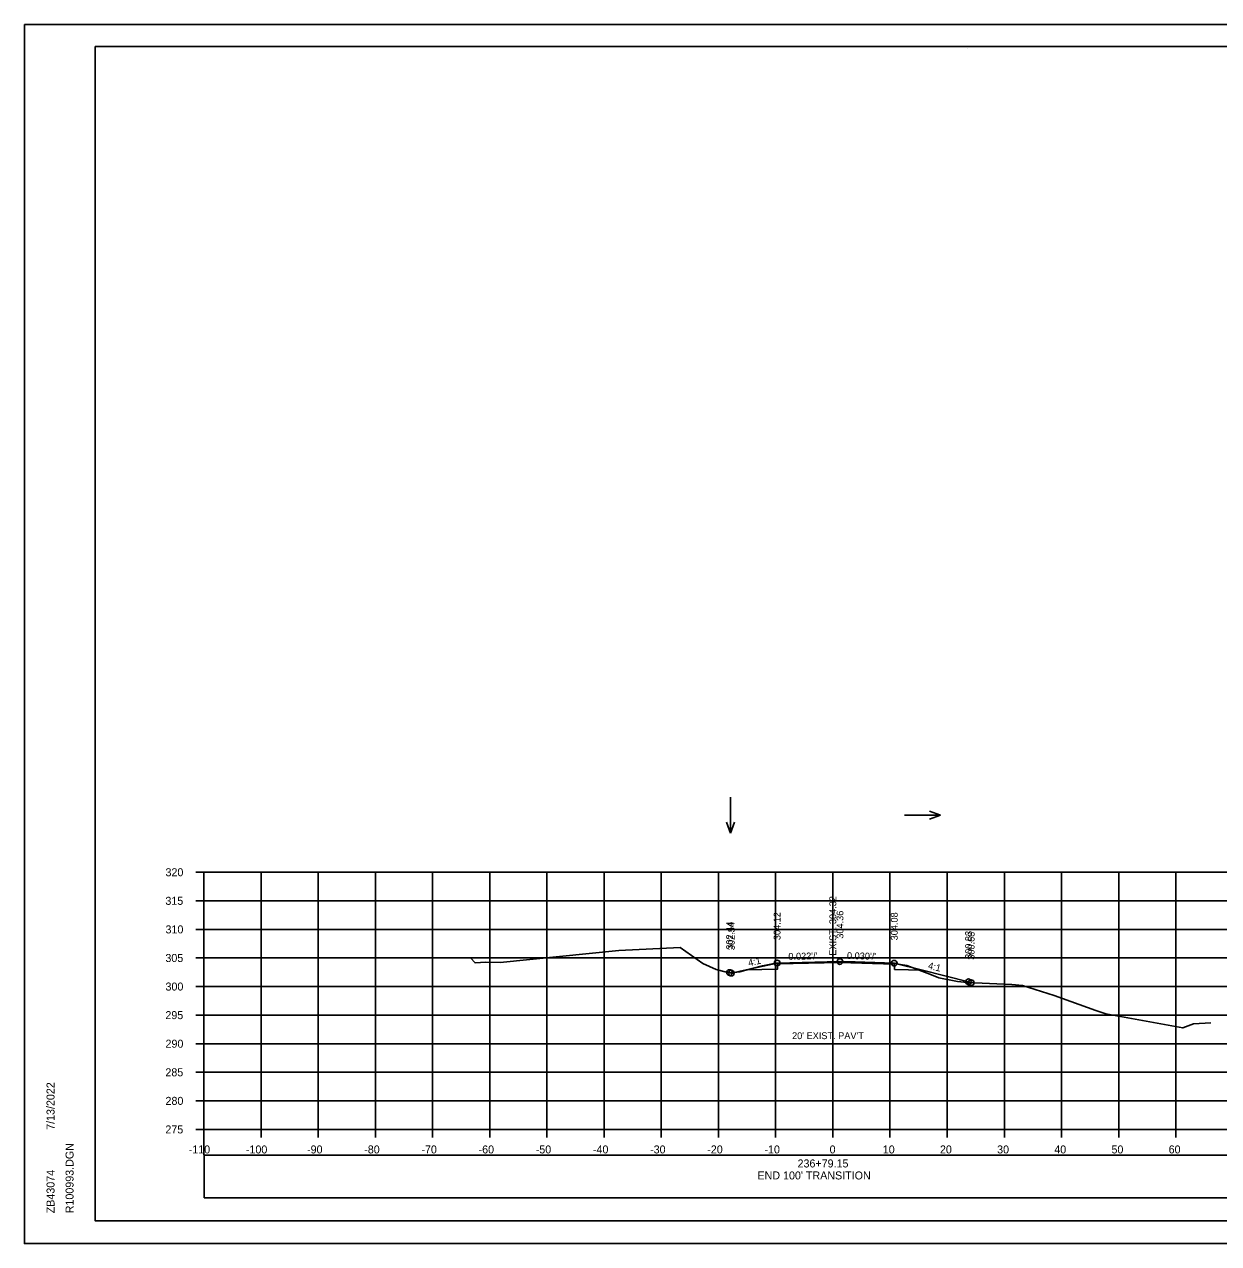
# Model space of a CAD drawing. Extents: x 4667 to 1632277, y -2100 to 724501.
# Drawn here: x 5635.8 to 5844.7, y 1663 to 1876.3 of the extents above; entities that cross this region are included whole.
import ezdxf

# ---------------------------------------------------------------- set-up
doc = ezdxf.new("R2010")
doc.units = 0
for name, color, linetype in [('R_Axis', 7, 'Continuous'), ('R_Axis Annot', 7, 'Continuous'), ('R_Border', 7, 'Continuous'), ('R_Exist Surface', 7, 'Continuous'), ('R_Grid', 7, 'Continuous'), ('R_No Plot', 7, 'Continuous'), ('R_Proposed CofA', 7, 'Continuous'), ('R_Temp Easement', 7, 'Continuous'), ('R_Water Annot', 7, 'Continuous')]:
    doc.layers.add(name, color=color, linetype=linetype)

msp = doc.modelspace()

# ---------------------------------------------------------------- linework, layer by layer
at = {"layer": 'R_Axis'}
for p, q in [((5665.78, 1727.96), (5667.18, 1727.96)), ((5667.18, 1682.96), (5667.18, 1727.96)), ((5665.78, 1722.96), (5667.18, 1722.96)), ((5665.78, 1717.96), (5667.18, 1717.96)), ((5665.78, 1712.96), (5667.18, 1712.96)), ((5665.78, 1707.96), (5667.18, 1707.96)), ((5665.78, 1702.96), (5667.18, 1702.96)), ((5665.78, 1697.96), (5667.18, 1697.96)), ((5665.78, 1692.96), (5667.18, 1692.96)), ((5665.78, 1687.96), (5667.18, 1687.96)), ((5665.78, 1682.96), (5667.18, 1682.96)), ((5667.18, 1682.96), (5947.18, 1682.96)), ((5667.18, 1681.56), (5667.18, 1682.96)), ((5677.18, 1681.56), (5677.18, 1682.96)), ((5687.18, 1681.56), (5687.18, 1682.96)), ((5697.18, 1681.56), (5697.18, 1682.96)), ((5707.18, 1681.56), (5707.18, 1682.96)), ((5717.18, 1681.56), (5717.18, 1682.96)), ((5727.18, 1681.56), (5727.18, 1682.96)), ((5737.18, 1681.56), (5737.18, 1682.96)), ((5747.18, 1681.56), (5747.18, 1682.96)), ((5757.18, 1681.56), (5757.18, 1682.96)), ((5767.18, 1681.56), (5767.18, 1682.96)), ((5777.18, 1681.56), (5777.18, 1682.96)), ((5787.18, 1681.56), (5787.18, 1682.96)), ((5797.18, 1681.56), (5797.18, 1682.96)), ((5807.18, 1681.56), (5807.18, 1682.96)), ((5817.18, 1681.56), (5817.18, 1682.96)), ((5827.18, 1681.56), (5827.18, 1682.96)), ((5837.18, 1681.56), (5837.18, 1682.96))]:
    msp.add_line(p, q, dxfattribs=at)
at = {"layer": 'R_Border'}
for p, q in [((5648.18, 1872.42), (5964.36, 1872.42)), ((5648.18, 1666.96), (5648.18, 1872.42)), ((5800.7, 1872.16), (5800.7, 1872.16)), ((5800.7, 1872.16), (5800.7, 1872.16)), ((5648.18, 1666.96), (5648.18, 1666.96)), ((5964.36, 1666.96), (5648.18, 1666.96))]:
    msp.add_line(p, q, dxfattribs=at)
at = {"layer": 'R_Exist Surface'}
msp.add_lwpolyline([(5713.79, 1713.01), (5714.61, 1712.1), (5716.47, 1712.21), (5719, 1712.19), (5739.75, 1714.26), (5750.46, 1714.78), (5754.47, 1712), (5756.78, 1710.92), (5758.37, 1710.51), (5759.27, 1710.39), (5760.39, 1710.48), (5760.9, 1710.52), (5761.94, 1710.81), (5764.87, 1711.61), (5766.91, 1711.98), (5767.48, 1712.08), (5775.36, 1712.23), (5778.44, 1712.32), (5781.07, 1712.26), (5787.97, 1712.03), (5788.67, 1711.9), (5790.12, 1711.67), (5794.17, 1710.14), (5795.72, 1709.5), (5799, 1708.86), (5800.68, 1708.68), (5808.5, 1708.3), (5810.38, 1708.14), (5815.92, 1706.42), (5823.21, 1703.75), (5824.92, 1703.2), (5838.39, 1700.73), (5840.24, 1701.45), (5843.3, 1701.62)], dxfattribs=at)
at = {"layer": 'R_Grid'}
for p, q in [((5667.18, 1727.96), (5947.18, 1727.96)), ((5667.18, 1682.96), (5667.18, 1727.96)), ((5677.18, 1682.96), (5677.18, 1727.96)), ((5687.18, 1682.96), (5687.18, 1727.96)), ((5697.18, 1682.96), (5697.18, 1727.96)), ((5707.18, 1682.96), (5707.18, 1727.96)), ((5717.18, 1682.96), (5717.18, 1727.96)), ((5727.18, 1682.96), (5727.18, 1727.96)), ((5737.18, 1682.96), (5737.18, 1727.96)), ((5747.18, 1682.96), (5747.18, 1727.96)), ((5757.18, 1682.96), (5757.18, 1727.96)), ((5767.18, 1682.96), (5767.18, 1727.96)), ((5777.18, 1682.96), (5777.18, 1727.96)), ((5787.18, 1682.96), (5787.18, 1727.96)), ((5797.18, 1682.96), (5797.18, 1727.96)), ((5807.18, 1682.96), (5807.18, 1727.96)), ((5817.18, 1682.96), (5817.18, 1727.96)), ((5827.18, 1682.96), (5827.18, 1727.96)), ((5837.18, 1682.96), (5837.18, 1727.96)), ((5667.18, 1722.96), (5947.18, 1722.96)), ((5667.18, 1717.96), (5947.18, 1717.96)), ((5667.18, 1712.96), (5947.18, 1712.96)), ((5667.18, 1707.96), (5947.18, 1707.96)), ((5667.18, 1702.96), (5947.18, 1702.96)), ((5667.18, 1697.96), (5947.18, 1697.96)), ((5667.18, 1692.96), (5947.18, 1692.96)), ((5667.18, 1687.96), (5947.18, 1687.96)), ((5667.18, 1682.96), (5947.18, 1682.96))]:
    msp.add_line(p, q, dxfattribs=at)
at = {"layer": 'R_No Plot'}
for p, q in [((5635.78, 1876.32), (5969.12, 1876.32)), ((5667.18, 1681.56), (5667.18, 1678.49)), ((5635.78, 1662.98), (5969.12, 1662.98))]:
    msp.add_line(p, q, dxfattribs=at)
for points in [[(5635.78, 1876.32), (5969.12, 1876.32), (5969.12, 1662.98), (5635.78, 1662.98)], [(5882.1, 1872.42), (5901.72, 1872.42), (5901.72, 1862.54), (5917.84, 1862.54), (5941.04, 1862.54), (5941.04, 1838.21), (5964.36, 1838.21), (5964.36, 1666.96), (5648.18, 1666.96), (5648.18, 1872.42)]]:
    msp.add_lwpolyline(points, close=True, dxfattribs=at)
for points in [[(5759.13, 1710.41), (5759.43, 1710.31), (5762.02, 1710.88), (5767.43, 1712.08), (5778.43, 1712.33), (5787.93, 1712.04), (5792.86, 1710.81), (5800.93, 1708.79), (5801.37, 1708.64)], [(5762.02, 1710.88), (5767.48, 1711), (5767.48, 1711.92), (5778.43, 1712.16), (5787.97, 1711.87), (5787.97, 1710.96), (5792.86, 1710.81)]]:
    msp.add_lwpolyline(points, dxfattribs=at)
for centre in [(5767.43, 1712.08), (5767.43, 1712.08), (5778.43, 1712.33), (5787.93, 1712.04), (5787.93, 1712.04), (5759.13, 1710.41), (5759.43, 1710.31), (5800.93, 1708.79), (5801.37, 1708.64)]:
    msp.add_circle(centre, 0.5, dxfattribs=at)
at = {"layer": 'R_Proposed CofA'}
msp.add_lwpolyline([(5667.23, 1671.02), (5947.13, 1671.02), (5947.13, 1678.44), (5667.23, 1678.44)], close=True, dxfattribs=at)
at = {"layer": 'R_Temp Easement'}
for p, q in [((5767.18, 1695.96), (5767.18, 1699.96)), ((5787.18, 1695.96), (5787.18, 1699.96)), ((5767.18, 1697.96), (5787.18, 1697.96))]:
    msp.add_line(p, q, dxfattribs=at)
at = {"layer": 'R_Water Annot'}
for p, q in [((5759.27, 1741.11), (5759.27, 1734.82)), ((5759.27, 1734.82), (5758.57, 1736.74)), ((5759.27, 1734.82), (5759.97, 1736.74)), ((5789.72, 1737.96), (5796, 1737.96)), ((5796, 1737.96), (5794.08, 1738.66)), ((5796, 1737.96), (5794.08, 1737.26))]:
    msp.add_line(p, q, dxfattribs=at)

# ---------------------------------------------------------------- texts
at = {"layer": 'R_Axis Annot'}
for s, p in [('320', (5660.46, 1727.26)), ('315', (5660.44, 1722.26)), ('310', (5660.46, 1717.26)), ('305', (5660.44, 1712.26)), ('300', (5660.46, 1707.26)), ('295', (5660.44, 1702.26)), ('290', (5660.46, 1697.26)), ('285', (5660.44, 1692.26)), ('280', (5660.46, 1687.26)), ('275', (5660.44, 1682.26)), ('-110', (5664.52, 1678.76)), ('-100', (5674.52, 1678.76)), ('-90', (5685.22, 1678.76)), ('-80', (5695.22, 1678.76)), ('-70', (5705.22, 1678.76)), ('-60', (5715.22, 1678.76)), ('-50', (5725.22, 1678.76)), ('-40', (5735.22, 1678.76)), ('-30', (5745.22, 1678.76)), ('-20', (5755.22, 1678.76)), ('-10', (5765.22, 1678.76)), ('0', (5776.62, 1678.76)), ('10', (5785.92, 1678.76)), ('20', (5795.92, 1678.76)), ('30', (5805.92, 1678.76)), ('40', (5815.92, 1678.76)), ('50', (5825.92, 1678.76)), ('60', (5835.92, 1678.76)), ('236+79.15', (5771.01, 1676.31)), ("END 100' TRANSITION", (5764, 1674.21))]:
    msp.add_text(s, height=1.4, dxfattribs=at).set_placement(p)
at = {"layer": 'R_Border'}
for s, p in [('7/13/2022', (5641.05, 1682.89)), ('R100993.DGN', (5644.38, 1668.29)), ('ZB43074', (5641.05, 1668.29))]:
    msp.add_text(s, height=1.4, rotation=90, dxfattribs=at).set_placement(p)
at = {"layer": 'R_No Plot'}
for s, rotation, p in [('304.12', 90, (5768.03, 1716.08)), ('304.12', 90, (5768.03, 1716.08)), ('304.36', 90, (5779.03, 1716.33)), ('304.08', 90, (5788.53, 1716.04)), ('304.08', 90, (5788.53, 1716.04)), ('302.44', 90, (5759.73, 1714.41)), ('302.34', 90, (5760.03, 1714.31)), ('300.83', 90, (5801.53, 1712.79)), ('300.68', 90, (5801.97, 1712.64)), ("0.022'/'", 1.2603, (5769.41, 1712.63)), ("0.030'/'", 358.2816, (5779.64, 1712.79)), ('4:1', 12.5288, (5762.51, 1711.5)), ('4:1', 345.9638, (5793.75, 1711.1))]:
    msp.add_text(s, height=1.2, rotation=rotation, dxfattribs=at).set_placement(p)
at = {"layer": 'R_Temp Easement'}
msp.add_text('EXIST. 304.32', height=1.2, rotation=90, dxfattribs=at).set_placement((5777.78, 1713.35))
msp.add_text("20' EXIST. PAV'T", height=1.2, dxfattribs=at).set_placement((5770.05, 1698.76))

doc.saveas('drawing.dxf')
